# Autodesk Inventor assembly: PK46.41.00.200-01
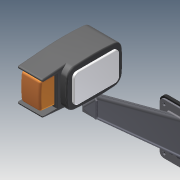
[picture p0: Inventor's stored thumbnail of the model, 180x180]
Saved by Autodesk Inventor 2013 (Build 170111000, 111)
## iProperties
Created: 2005-07
Part Number: PK46.41.00.200-01
Document SubType Name: Assembly
Designer: PVitaliy
Manufacturer: Standard
Standards Organization: Custom
Author: PVitaliy
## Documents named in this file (11)
- D:\FrontLoaderVault\Data\Assy, Chassis, Front\PK46.41.00.200-01.iam
- D:\FrontLoaderVault\Data\Assy, Chassis, Front\05.483.000-01.ipt
- D:\FrontLoaderVault\Data\Assy, Chassis, Front\D395A-0401269-01.ipt
- D:\FrontLoaderVault\Data\Assy, Chassis, Front\PK46.41.00.210-01.iam
- D:\FrontLoaderVault\Data\Assy, Chassis, Rear\10.65G.019.ipt
- D:\FrontLoaderVault\Data\Assy, Chassis, Rear\M10-6H.5.019(S16).ipt
- D:\FrontLoaderVault\Data\Assy, Chassis, Front\D395A-0401270.ipt
- D:\FrontLoaderVault\Data\Assy, Chassis, Front\PK46.41.00.012A.ipt
- 10.65G.019.ipt
- M10-6H.5.019(S16).ipt
- PK46.41.00.012A.ipt
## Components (7 placed, 7 different names)
1. PK46.41.00.210-01:1 [sub-assembly] — Вставка:1, Вставка:6, Insert:7, Insert:8, Insert:9, Insert:11
2. 05.483.000-01:1 — Вставка:1
3. PK46.41.00.012A:1 — Insert:7, Insert:8
4. D395A-0401269-01:1 — Вставка:6
5. 10.65G.019:1 — Insert:9, Insert:10
6. M10-6H.5.019(S16):1 — Insert:10
7. D395A-0401270:1 — Insert:11
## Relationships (7: Insert 7)
- Вставка:1 [Insert]: PK46.41.00.210-01:1 ↔ 05.483.000-01:1
- Вставка:6 [Insert]: PK46.41.00.210-01:1 ↔ D395A-0401269-01:1
- Insert:7: PK46.41.00.210-01:1 ↔ PK46.41.00.012A:1
- Insert:8: PK46.41.00.210-01:1 ↔ PK46.41.00.012A:1
- Insert:9: PK46.41.00.210-01:1 ↔ 10.65G.019:1
- Insert:10: 10.65G.019:1 ↔ M10-6H.5.019(S16):1
- Insert:11: PK46.41.00.210-01:1 ↔ D395A-0401270:1
